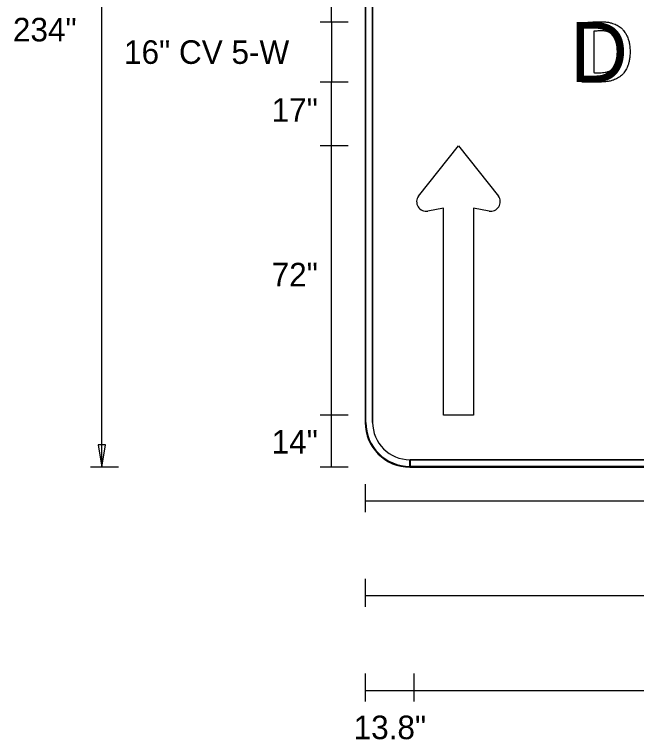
# Model space of a CAD drawing. Extents: x 531799 to 532094, y 1531149 to 1533620.
# Drawn here: x 531807.27 to 531822.99, y 1531200.2 to 1531218.51 of the extents above; entities that cross this region are included whole.
import ezdxf

# ---------------------------------------------------------------- set-up
doc = ezdxf.new("R2010")
doc.units = 0
for name, color, linetype in [('GSBWFill', 7, 'Continuous'), ('GSColorFill', 7, 'Continuous'), ('GSDims', 7, 'Continuous'), ('GSOutline', 7, 'Continuous'), ('SignPanel', 7, 'Continuous')]:
    doc.layers.add(name, color=color, linetype=linetype)

msp = doc.modelspace()

# ---------------------------------------------------------------- linework, layer by layer
at = {"layer": 'GSDims'}
for p, q in [((531809.479, 1531207.076), (531809.479, 1531229.171)), ((531815.28, 1531218.312), (531815.28, 1531219.445)), ((531815.705, 1531218.312), (531814.997, 1531218.312)), ((531815.705, 1531218.312), (531814.997, 1531218.312)), ((531815.28, 1531218.312), (531815.28, 1531216.801)), ((531815.705, 1531216.801), (531814.997, 1531216.801)), ((531815.705, 1531216.801), (531814.997, 1531216.801)), ((531815.28, 1531207.076), (531815.28, 1531216.801)), ((531815.705, 1531215.191), (531814.997, 1531215.191)), ((531815.705, 1531208.393), (531814.997, 1531208.393)), ((531809.904, 1531207.076), (531809.196, 1531207.076)), ((531815.705, 1531207.076), (531814.997, 1531207.076)), ((531816.13, 1531206.651), (531816.13, 1531205.943)), ((531816.13, 1531206.226), (531821.609, 1531206.226)), ((531821.609, 1531206.226), (531865.814, 1531206.226)), ((531816.13, 1531204.259), (531816.13, 1531203.551)), ((531816.13, 1531203.835), (531821.609, 1531203.835)), ((531821.609, 1531203.835), (531865.814, 1531203.835)), ((531816.13, 1531201.868), (531816.13, 1531201.16)), ((531817.357, 1531201.868), (531817.357, 1531201.16)), ((531816.13, 1531201.443), (531821.609, 1531201.443)), ((531821.609, 1531201.443), (531865.814, 1531201.443))]:
    msp.add_line(p, q, dxfattribs=at)
msp.add_lwpolyline([(531809.479, 1531207.076), (531809.573, 1531207.642), (531809.385, 1531207.642)], close=True, dxfattribs=at)
at = {"layer": 'GSOutline'}
for p, q in [((531816.13, 1531228.038), (531816.13, 1531208.209)), ((531816.319, 1531228.038), (531816.319, 1531208.209)), ((531817.263, 1531207.265), (531865.985, 1531207.265)), ((531817.263, 1531207.076), (531865.985, 1531207.076))]:
    msp.add_line(p, q, dxfattribs=at)
for points in [[(531822.094, 1531216.801), (531821.61, 1531216.801), (531821.61, 1531218.298)], [(531821.904, 1531218.082), (531821.904, 1531217.037)]]:
    msp.add_lwpolyline(points, dxfattribs=at)
for radius in [1.133, 0.944]:
    msp.add_arc((531817.263, 1531208.209), radius, 180, 270, dxfattribs=at)
for points in [[(531821.61, 1531218.298), (531821.628, 1531218.299), (531821.666, 1531218.302), (531821.724, 1531218.308), (531821.786, 1531218.312), (531821.849, 1531218.316), (531821.913, 1531218.319), (531821.976, 1531218.321), (531822.037, 1531218.323), (531822.077, 1531218.323), (531822.096, 1531218.323)], [(531822.096, 1531218.323), (531822.123, 1531218.323), (531822.202, 1531218.321), (531822.304, 1531218.305), (531822.388, 1531218.281), (531822.444, 1531218.261), (531822.496, 1531218.236), (531822.553, 1531218.201), (531822.597, 1531218.166), (531822.629, 1531218.135), (531822.659, 1531218.102), (531822.694, 1531218.057), (531822.73, 1531217.997), (531822.755, 1531217.943), (531822.777, 1531217.885), (531822.804, 1531217.793), (531822.82, 1531217.68), (531822.822, 1531217.593), (531822.823, 1531217.562)], [(531822.109, 1531218.091), (531822.092, 1531218.091), (531822.058, 1531218.091), (531822.006, 1531218.09), (531821.955, 1531218.087), (531821.921, 1531218.084), (531821.904, 1531218.082)], [(531822.515, 1531217.567), (531822.515, 1531217.588), (531822.514, 1531217.63), (531822.51, 1531217.693), (531822.502, 1531217.755), (531822.49, 1531217.806), (531822.475, 1531217.853), (531822.46, 1531217.89), (531822.441, 1531217.924), (531822.42, 1531217.956), (531822.395, 1531217.986), (531822.37, 1531218.008), (531822.339, 1531218.033), (531822.302, 1531218.054), (531822.258, 1531218.071), (531822.212, 1531218.083), (531822.162, 1531218.09), (531822.123, 1531218.091), (531822.109, 1531218.091)], [(531822.059, 1531217.036), (531822.077, 1531217.036), (531822.128, 1531217.037), (531822.193, 1531217.045), (531822.247, 1531217.059), (531822.282, 1531217.07), (531822.314, 1531217.084), (531822.35, 1531217.106), (531822.378, 1531217.128), (531822.398, 1531217.148), (531822.417, 1531217.169), (531822.438, 1531217.2), (531822.46, 1531217.241), (531822.475, 1531217.279), (531822.489, 1531217.32), (531822.505, 1531217.389), (531822.514, 1531217.475), (531822.515, 1531217.542), (531822.515, 1531217.567)], [(531822.823, 1531217.562), (531822.822, 1531217.532), (531822.821, 1531217.447), (531822.805, 1531217.338), (531822.781, 1531217.249), (531822.76, 1531217.191), (531822.736, 1531217.137), (531822.701, 1531217.077), (531822.668, 1531217.032), (531822.638, 1531216.998), (531822.606, 1531216.967), (531822.563, 1531216.932), (531822.506, 1531216.895), (531822.454, 1531216.869), (531822.41, 1531216.852), (531822.324, 1531216.823), (531822.218, 1531216.804), (531822.123, 1531216.802), (531822.094, 1531216.801)], [(531821.904, 1531217.037), (531821.919, 1531217.037), (531821.946, 1531217.036), (531821.973, 1531217.036), (531821.986, 1531217.036)], [(531821.986, 1531217.036), (531821.998, 1531217.036), (531822.022, 1531217.036), (531822.047, 1531217.036), (531822.059, 1531217.036)]]:
    msp.add_open_spline(points, degree=3, dxfattribs=at)
at = {"layer": 'SignPanel'}
for p, q in [((531816.13, 1531228.038), (531816.13, 1531208.209)), ((531816.13, 1531228.038), (531816.13, 1531208.209)), ((531816.13, 1531228.038), (531816.13, 1531208.209)), ((531816.13, 1531228.038), (531816.13, 1531208.209)), ((531816.149, 1531208.209), (531816.149, 1531228.038)), ((531816.319, 1531208.209), (531816.319, 1531228.038)), ((531816.319, 1531208.209), (531816.319, 1531228.038)), ((531817.479, 1531213.923), (531818.489, 1531215.191)), ((531818.489, 1531215.191), (531819.499, 1531213.923)), ((531817.263, 1531207.076), (531817.263, 1531207.265)), ((531817.263, 1531207.076), (531817.263, 1531207.265)), ((531865.985, 1531207.265), (531817.265, 1531207.265)), ((531817.265, 1531207.265), (531817.265, 1531207.076)), ((531865.985, 1531207.265), (531817.265, 1531207.265)), ((531817.265, 1531207.265), (531817.265, 1531207.076)), ((531817.263, 1531207.076), (531817.263, 1531207.095)), ((531865.985, 1531207.095), (531817.263, 1531207.095)), ((531817.263, 1531207.095), (531817.263, 1531207.076)), ((531817.263, 1531207.076), (531865.985, 1531207.076)), ((531817.263, 1531207.076), (531865.985, 1531207.076)), ((531817.265, 1531207.076), (531865.985, 1531207.076)), ((531817.265, 1531207.076), (531865.985, 1531207.076))]:
    msp.add_line(p, q, dxfattribs=at)
msp.add_lwpolyline([(531819.261, 1531213.543), (531818.867, 1531213.615), (531818.867, 1531208.393), (531818.111, 1531208.393), (531818.111, 1531213.615), (531817.717, 1531213.543)], dxfattribs=at)
for centre, radius, start, end in [((531817.673, 1531213.78), 0.241, 143.6981, 280.3296), ((531819.304, 1531213.78), 0.241, 259.6704, 36.3019), ((531817.263, 1531208.209), 1.133, 180, 270), ((531817.263, 1531208.209), 1.133, 180, 270), ((531817.263, 1531208.209), 1.133, 180, 270), ((531817.263, 1531208.209), 1.133, 180, 270), ((531817.263, 1531208.209), 1.114, 180, 270), ((531817.263, 1531208.209), 0.944, 180, 270), ((531817.263, 1531208.209), 0.944, 180, 270)]:
    msp.add_arc(centre, radius, start, end, dxfattribs=at)

# ---------------------------------------------------------------- texts
at = {"layer": 'GSBWFill'}
msp.add_text('D', height=1.511, dxfattribs=at).set_placement((531821.308, 1531216.801))
at = {"layer": 'GSColorFill'}
msp.add_text('D', height=1.511, dxfattribs=at).set_placement((531821.308, 1531216.801))
at = {"layer": 'GSDims'}
msp.add_text('234"', height=0.595, rotation=360, dxfattribs=at).set_placement((531807.233, 1531217.826))
for s, p in [('16" CV 5-W', (531810.04, 1531217.259)), ('17"', (531813.769, 1531215.797)), ('72"', (531813.769, 1531211.641)), ('14"', (531813.769, 1531207.419)), ('13.8"', (531815.84, 1531200.21))]:
    msp.add_text(s, height=0.595, dxfattribs=at).set_placement(p)

doc.saveas('drawing.dxf')
